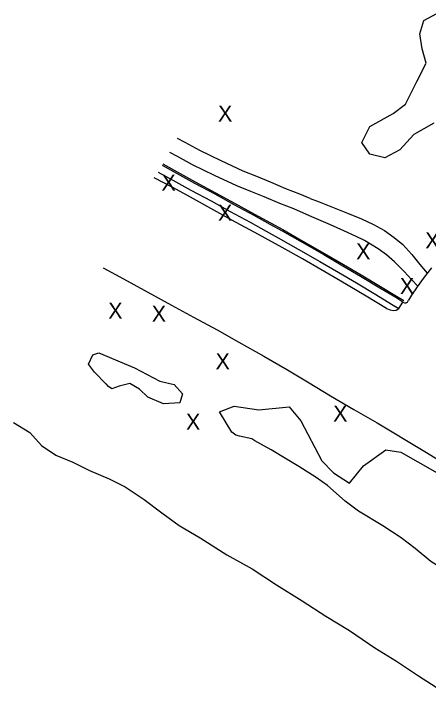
# Model space of a CAD drawing. Extents: x 2023750 to 2025732, y 819696 to 821148.
# Drawn here: x 2023749.6 to 2024009.1, y 820723.4 to 821148.1 of the extents above; entities that cross this region are included whole.
import ezdxf

# ---------------------------------------------------------------- set-up
doc = ezdxf.new("R2010")
doc.units = 0
for name, color, linetype in [('Old_Level_19', 7, 'Continuous'), ('Old_Level_2', 7, 'Continuous'), ('Old_Level_26', 7, 'Continuous')]:
    doc.layers.add(name, color=color, linetype=linetype)

msp = doc.modelspace()

# ---------------------------------------------------------------- linework, layer by layer
at = {"layer": 'Old_Level_19'}
msp.add_lwpolyline([(2023842.87, 821054.03), (2023853.88, 821047.96), (2023863.17, 821042.72), (2023875.83, 821036), (2023887.82, 821029.43), (2023900.27, 821022.65), (2023910.28, 821017.12), (2023917.94, 821012.9), (2023930.46, 821005.72), (2023943.97, 820998.05), (2023955.95, 820991.03), (2023966.97, 820984.55), (2023979.08, 820977.24), (2023989.08, 820971.35), (2023993.6, 820968.52)], dxfattribs=at)
at = {"layer": 'Old_Level_2'}
for points in [[(2024012.52, 821079.55), (2023999.98, 821072.47), (2023991.19, 821062.77), (2023981.81, 821057.92), (2023972.34, 821060.05), (2023967.32, 821067.32), (2023972.45, 821077.34), (2023986.98, 821085.48), (2023994.63, 821091.41), (2024001.78, 821105.61), (2024007.63, 821117.1), (2024005.18, 821125.97), (2024003.69, 821135.3), (2024006.26, 821143.64), (2024014.37, 821148.05)], [(2023807.43, 820916.32), (2023800.11, 820923.83), (2023796.51, 820928.72), (2023799.25, 820934.61), (2023802.83, 820935.79), (2023825.3, 820926.47), (2023841.15, 820918.08), (2023849.94, 820916.08), (2023855.26, 820910.23), (2023853.61, 820904.49), (2023843.44, 820904.04), (2023833.53, 820908.19), (2023828.4, 820913.04), (2023822.21, 820916.6), (2023815.58, 820914.92), (2023811.11, 820913.27), (2023809.03, 820914.7), (2023807.51, 820916.48)], [(2023886.16, 820886.12), (2023878.35, 820898.89), (2023878.35, 820898.89), (2023887.64, 820902.52), (2023903.04, 820900.1), (2023922.01, 820902.04), (2023929.17, 820893.3), (2023942.31, 820868.19), (2023949.68, 820860.87), (2023959.71, 820854.36), (2023968.53, 820865.07), (2023982.43, 820875.07), (2023991.72, 820873.8), (2024025.1, 820854.78), (2024027.46, 820845.38), (2024020.57, 820831.53), (2024018.12, 820823.89), (2024023.71, 820818.43), (2024047.88, 820805.79), (2024075.43, 820785.98), (2024099.53, 820766.28), (2024118.22, 820752.93)], [(2023749.58, 820892.2), (2023759.7, 820886.01), (2023766.97, 820877.8), (2023776.07, 820871.86), (2023786.73, 820867.36), (2023796.97, 820862.24), (2023809.35, 820856.95), (2023819.46, 820851.99), (2023831.19, 820844.2), (2023842.23, 820835.74), (2023853.25, 820827.76), (2023866.31, 820820.15), (2023883, 820809.54), (2023898.91, 820800.65), (2023914.02, 820790.78), (2023930.11, 820780.68), (2023944.85, 820771.1), (2023959.78, 820762.16), (2023975.51, 820751.38), (2023989.03, 820742.91), (2024002.83, 820733.88), (2024019.06, 820723.43)], [(2024107.02, 820738.73), (2024096.09, 820744.78), (2024082.45, 820755.07), (2024069.06, 820764.85), (2024056.73, 820774.58), (2024046.56, 820781.21), (2024033.7, 820791.38), (2024022.86, 820797.53), (2024010.47, 820805.25), (2024000.84, 820813.49), (2023992.04, 820820.2), (2023980.53, 820827.57), (2023965.36, 820836.87), (2023957.03, 820843), (2023945.88, 820852.87), (2023938.79, 820857.9), (2023928.07, 820864.71), (2023919.76, 820869.73), (2023910.71, 820875.08), (2023900.57, 820880.81), (2023898.64, 820881.99), (2023890.98, 820883.78), (2023888.59, 820884.24), (2023886.16, 820886.12)]]:
    msp.add_lwpolyline(points, dxfattribs=at)
at = {"layer": 'Old_Level_26'}
for points in [[(2023935.06, 821032.35), (2023928.59, 821035.18), (2023919.95, 821038.52), (2023910.21, 821042.64), (2023901.63, 821046.04), (2023893.18, 821049.49), (2023879.48, 821055.86), (2023866.17, 821062.34), (2023856.99, 821067.35), (2023852.11, 821069.99)], [(2023987.89, 820992.67), (2023982.74, 820997.21), (2023977.64, 821000.86), (2023973.96, 821003.29), (2023969.07, 821006.04), (2023963.38, 821008.8), (2023956.08, 821012.17), (2023947.89, 821015.87), (2023934.66, 821021.6), (2023924.78, 821025.92), (2023916.19, 821029.24), (2023906.41, 821033.38), (2023897.9, 821036.75), (2023889.17, 821040.32), (2023875.18, 821046.82), (2023861.57, 821053.44), (2023852.21, 821058.55), (2023847.35, 821061.18)], [(2023842.46, 821053.28), (2023853.46, 821047.22), (2023862.76, 821041.97), (2023875.42, 821035.25), (2023887.41, 821028.68), (2023899.86, 821021.9), (2023909.86, 821016.38), (2023917.52, 821012.15), (2023930.04, 821004.97), (2023943.54, 820997.3), (2023955.52, 820990.3), (2023966.53, 820983.81), (2023978.64, 820976.51), (2023988.64, 820970.61), (2023993.14, 820967.8)], [(2023840.06, 821048.94), (2023851.05, 821042.88), (2023860.38, 821037.62), (2023873.07, 821030.88), (2023885.03, 821024.33), (2023897.47, 821017.55), (2023907.47, 821012.03), (2023915.09, 821007.83), (2023927.58, 821000.67), (2023941.06, 820993.01), (2023953.01, 820986.02), (2023963.99, 820979.55), (2023976.1, 820972.25), (2023986.06, 820966.37), (2023990.51, 820963.59)], [(2023982.9, 820963.61), (2023970.02, 820971.36), (2023954.17, 820980.62), (2023941.81, 820987.9), (2023930.19, 820994.67), (2023917.66, 821001.73), (2023902.72, 821009.91), (2023886.02, 821018.77), (2023874.78, 821025), (2023860.15, 821033.19), (2023849.28, 821039.19), (2023837.62, 821045.34)], [(2023935.06, 821032.35), (2023940.74, 821030.2), (2023950.15, 821026.46), (2023958.41, 821023.14), (2023967.16, 821019.56), (2023974.8, 821016.15), (2023981.58, 821012.43), (2023987.7, 821007.98), (2023993.05, 821003.63), (2023998.74, 820997.4), (2024003.78, 820991.1)], [(2024002.35, 820977.55), (2023998.41, 820981.79), (2023993.94, 820986.66), (2023987.89, 820992.67)], [(2024003.78, 820991.1), (2024008.17, 820985.75)], [(2023805.72, 820988.93), (2023818.39, 820982.15), (2023831.36, 820975.11), (2023848.38, 820965.73), (2023862.12, 820958.11), (2023876.83, 820950.33), (2023890.52, 820942.43), (2023906.1, 820933.75), (2023920.81, 820925.24), (2023934.42, 820917.09), (2023947.89, 820908.97), (2023962.46, 820900.34), (2023976.94, 820892.01), (2024006.81, 820874.03), (2024022.39, 820864.6)], [(2024010.98, 820989.03), (2024006.31, 820983.08), (2024002.09, 820977.04), (2023998.39, 820971.98), (2023996.55, 820968.74)], [(2023982.9, 820963.61), (2023985.12, 820962.71), (2023987.1, 820962.42), (2023988.88, 820962.61), (2023990.51, 820963.59), (2023993.06, 820967.58)], [(2023993.06, 820967.58), (2023994.12, 820967.07), (2023995.09, 820967.09), (2023995.92, 820967.63), (2023996.55, 820968.74)]]:
    msp.add_lwpolyline(points, dxfattribs=at)

# ---------------------------------------------------------------- texts
at = {"layer": 'Old_Level_2'}
for p in [(2023877.46, 821080.54), (2023842.06, 821037.34), (2023877.4, 821018.44), (2024007.08, 821001.15), (2023963.84, 820994.34), (2023991.2, 820972.62), (2023808.8, 820957.2), (2023836.01, 820955.3), (2023875.93, 820925.56), (2023949.46, 820892.89), (2023857.44, 820887.74)]:
    msp.add_text('X', height=10, dxfattribs=at).set_placement(p)

doc.saveas('drawing.dxf')
